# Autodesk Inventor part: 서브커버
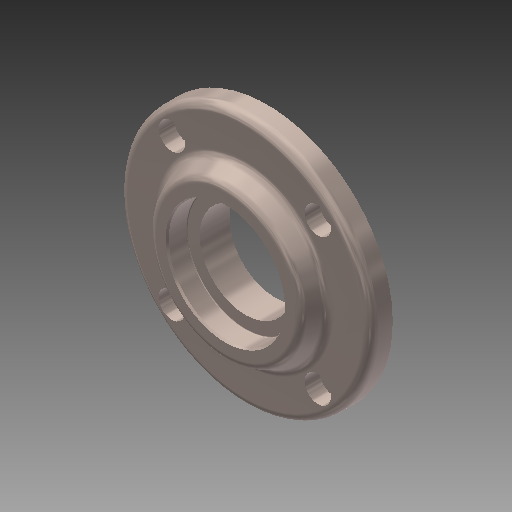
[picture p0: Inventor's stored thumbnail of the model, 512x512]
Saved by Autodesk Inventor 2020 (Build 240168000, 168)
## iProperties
Created: 2013-01
Part Number: 서브커버
Document SubType Name: Modeling
Designer: 한국산업디자인학원[gmhk.co.kr]
Density: 7.25 g/cm^3
Material: 주철
Mass: 439.929 g
Surface Area: 178.476 cm^2
Volume: 60.6798 cm^3
Appearance: 강철(1)
Author: 한국산업디자인학원[gmhk.co.kr]
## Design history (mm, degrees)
sketch "스케치2"
  geometry: L1 (-45, 0)-(0, 0); L2 (-25.784, -7)-(25.784, -7) reference; L3 (0, -7)-(0, 15); L4 (-31, -23)-(-31, 0) reference; L5 (-26.5, -7)-(-26.5, -3); L6 (-26.5, -3)-(0, -3); L7 (-26.5, -7)-(-31, -7); L8 (-31, 0)-(-45, 0); L9 (-45, 0)-(-45, 8); L10 (-45, 8)-(-30, 8); L11 (-30, 8)-(-26.736, 15); L12 (-26.736, 15)-(0, 15)
  constraints: 25 end point, 6 perpendicular, 3 point on line, 1 collinear, 1 horizontal, 1 midpoint, 1 parallel, 1 vertical, 3 other
  dimensions: "d0" = 53 diameter of L5 L3; "d1" = 4 distance between parallel lines of L6 L2; "d2" = 8 distance between parallel lines of L10 L1; "d3" = 7 distance between parallel lines of L12 L10; "d4" = 60 diameter of L10.end L3; "d5" = 115 deg angle of L11 L10; "d27" = 90 diameter of L9 L3
revolve "회전1" sketch "스케치2" stored, may be unused: angle "d6" = 90 deg
hole "구멍1" diameter "d9" = 33; stored, may be unused: countersink angle "d13" = 90 deg, drill point angle "d15" = 118 deg; dims "d10" = 6, "d11" = 42, "d12" = 7.3, "d14" = 8, "d38" = 10, "d39" = 10
fillet "모깎기1" dims "d16" = 3
chamfer "모따기1" distance "d17" = 0.7; stored, may be unused: second distance "d18" = 2, angle "d19" = 30 deg
sketch "스케치3"
  geometry: C1 r 2.067 at (26.163, 26.163) reference; 1 further point
hole "구멍2" sketch "스케치3" at (26.163, 26.163) diameter "d20" = 5.4; stored, may be unused: countersink angle "d24" = 90 deg, drill point angle "d26" = 118 deg; dims "d21" = 6, "d22" = 9.5, "d23" = 5.5, "d25" = 8
fillet "모깎기2" dims "d31" = 0.3
fillet "모깎기3" dims "d32" = 3
chamfer "모따기2" distance "d35" = 1; stored, may be unused: second distance "d36" = 2, angle "d37" = 45 deg
node "솔리드1"
pattern_circular "원형 패턴1" dims angle "d29" = 360 deg
node "참조3"
